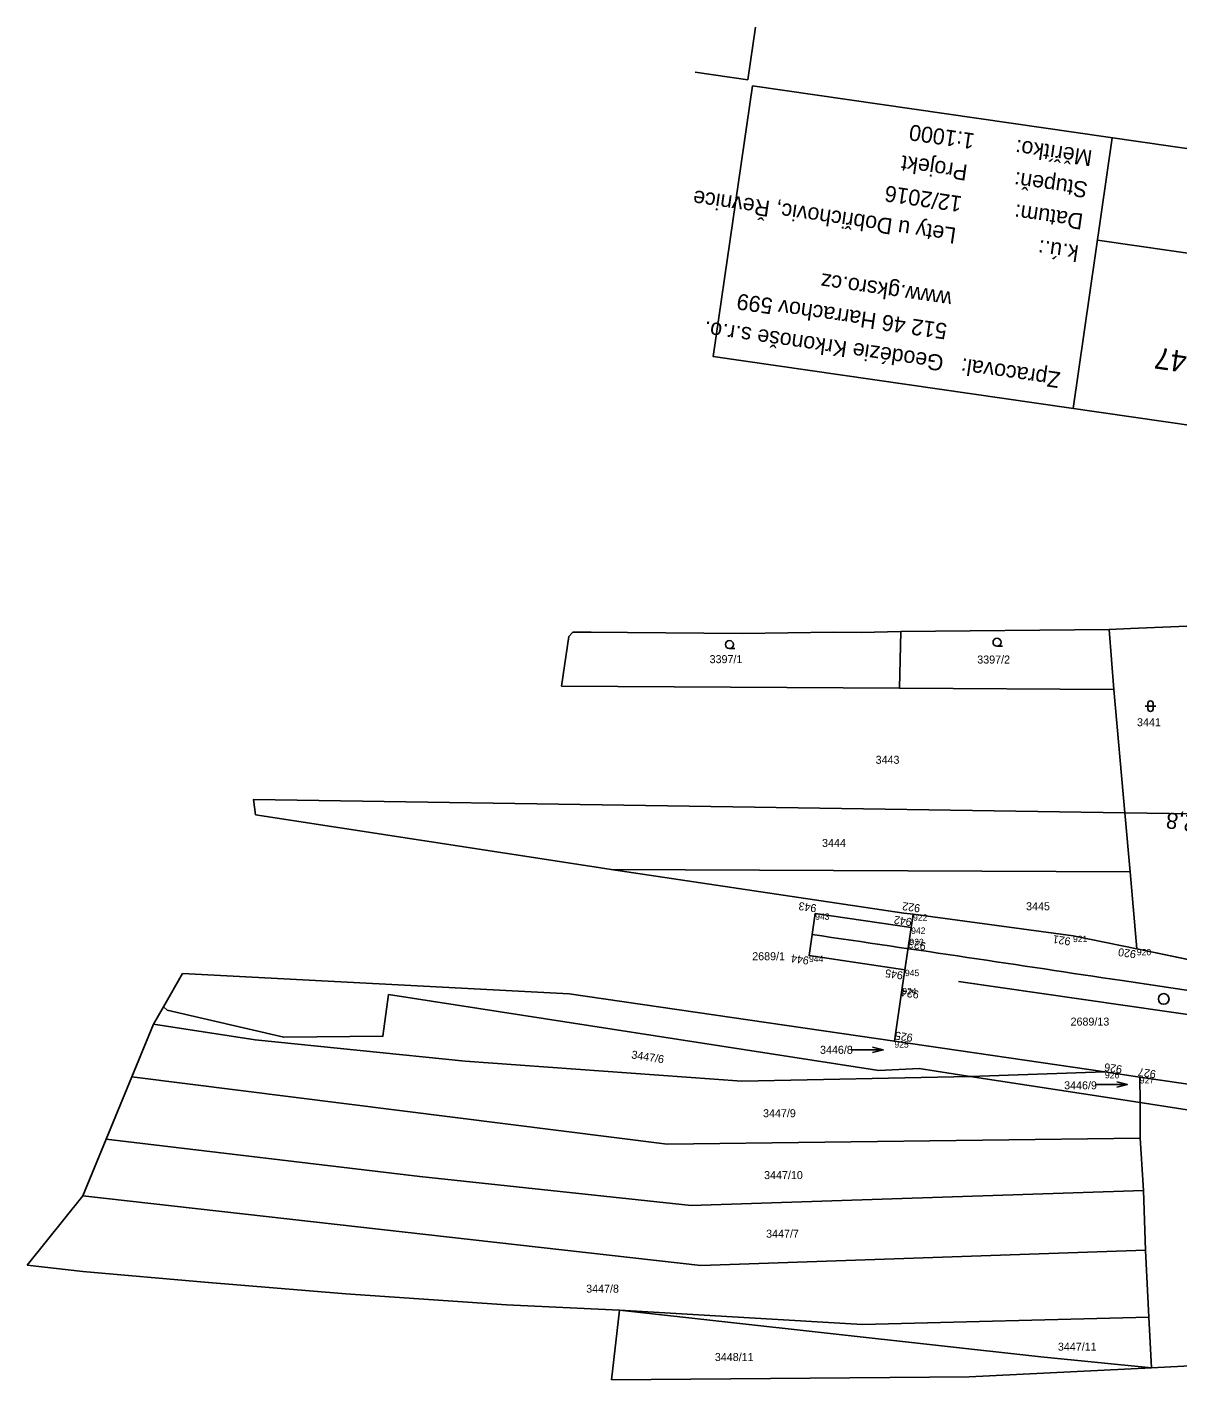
# Model space of a CAD drawing. Extents: x -757895 to -757311, y -1060303 to -1059942.
# Drawn here: x -757895.1 to -757679.5, y -1060195.2 to -1059941.6 of the extents above; entities that cross this region are included whole.
import ezdxf

# ---------------------------------------------------------------- set-up
doc = ezdxf.new("R2010")
doc.units = 0
for name, color, linetype in [('_hektaky', 7, 'Continuous'), ('_SO 102 hektometry', 7, 'Continuous'), ('Dočasné zábory', 7, 'Continuous'), ('Legenda 1', 7, 'Continuous'), ('Obvod stavby', 7, 'Continuous'), ('Vrstva 1', 7, 'Continuous'), ('Vrstva 53', 7, 'Continuous'), ('Vrstva 55', 7, 'Continuous'), ('Vrstva 57', 7, 'Continuous'), ('Vrstva 58', 7, 'Continuous'), ('Vrstva 60', 7, 'Continuous')]:
    doc.layers.add(name, color=color, linetype=linetype)

msp = doc.modelspace()

# ---------------------------------------------------------------- linework, layer by layer
at = {"layer": '_SO 102 hektometry'}
msp.add_circle((-757682.17, -1060123.76), 1, dxfattribs=at)
at = {"layer": 'Dočasné zábory'}
msp.add_lwpolyline([(-757730.65, -1060118.28), (-757729.8, -1060112.49), (-757729.49, -1060110.36), (-757747.46, -1060107.72), (-757748.62, -1060115.63), (-757730.65, -1060118.28)], dxfattribs=at)
at = {"layer": 'Legenda 1'}
for p, q in [((-757758.65, -1059941.6), (-757760.08, -1059951.5)), ((-757769.98, -1059950.07), (-757760.08, -1059951.5)), ((-757691.8, -1059962.36), (-757699.12, -1060013.09)), ((-757694.57, -1059981.56), (-757587.21, -1059997.05))]:
    msp.add_line(p, q, dxfattribs=at)
msp.add_lwpolyline([(-757759.23, -1059952.63), (-757584.43, -1059977.86), (-757591.76, -1060028.59), (-757766.56, -1060003.36)], close=True, dxfattribs=at)
at = {"layer": 'Obvod stavby'}
msp.add_lwpolyline([(-757639.93, -1060124.17), (-757687.19, -1060114.38), (-757699.16, -1060111.9), (-757729.12, -1060107.89), (-757729.8, -1060112.49), (-757731.15, -1060121.69), (-757732.62, -1060131.67), (-757693.18, -1060137.43), (-757686.64, -1060138.39), (-757635.44, -1060145.86)], dxfattribs=at)
at = {"layer": 'Vrstva 1'}
for p, q in [((-757429.32, -1060162.53), (-757720.62, -1060120.47)), ((-757665.26, -1060124.05), (-757689.98, -1060120.32))]:
    msp.add_line(p, q, dxfattribs=at)
msp.add_arc((-759559.14, -1072479.78), 12500, 81.400126, 81.669213, dxfattribs=at)
at = {"layer": 'Vrstva 53'}
for points in [[(-757852.31, -1060089.26), (-757789.66, -1060098.89), (-757785.7, -1060099.48), (-757730.83, -1060107.66), (-757729.12, -1060107.89), (-757699.16, -1060111.9), (-757687.19, -1060114.38), (-757639.93, -1060124.17)], [(-757328.56, -1060183.46), (-757338.29, -1060184.85), (-757361.91, -1060181.63), (-757443.58, -1060171.99), (-757470.38, -1060167.04), (-757513.1, -1060164.5), (-757526.21, -1060162.71), (-757533.6, -1060161.43), (-757535.01, -1060161.18), (-757542.9, -1060160.49), (-757543.88, -1060160.4), (-757632.1, -1060146.3), (-757634.26, -1060145.96), (-757635.44, -1060145.86), (-757686.64, -1060138.39), (-757693.18, -1060137.43), (-757732.62, -1060131.67), (-757793.56, -1060122.78), (-757866, -1060118.97)]]:
    msp.add_lwpolyline(points, dxfattribs=at)
at = {"layer": 'Vrstva 55'}
for p, q in [((-757688.39, -1060054.34), (-757677.84, -1060053.89)), ((-757794.99, -1060065.12), (-757793.62, -1060055.81)), ((-757761.16, -1060055.23), (-757782.62, -1060055.08)), ((-757731.45, -1060054.87), (-757738.86, -1060055.09)), ((-757731.69, -1060065.52), (-757731.45, -1060054.87)), ((-757692.38, -1060054.51), (-757731.45, -1060054.87)), ((-757692.38, -1060054.51), (-757688.39, -1060054.34)), ((-757691.5, -1060065.78), (-757692.38, -1060054.51)), ((-757794.99, -1060065.12), (-757731.69, -1060065.52)), ((-757731.69, -1060065.52), (-757691.5, -1060065.78)), ((-757691.5, -1060065.78), (-757689.45, -1060088.87)), ((-757689.45, -1060088.87), (-757688.47, -1060099.93)), ((-757689.45, -1060088.87), (-757676.88, -1060089.06)), ((-757785.7, -1060099.48), (-757688.47, -1060099.93)), ((-757688.47, -1060099.93), (-757687.19, -1060114.38)), ((-757687.19, -1060114.38), (-757639.93, -1060124.17)), ((-757869.56, -1060125.23), (-757866, -1060118.97)), ((-757866, -1060118.97), (-757793.56, -1060122.78)), ((-757793.56, -1060122.78), (-757732.62, -1060131.67)), ((-757871.42, -1060128.49), (-757869.56, -1060125.23)), ((-757875.47, -1060138.34), (-757871.42, -1060128.49)), ((-757693.18, -1060137.43), (-757732.62, -1060131.67)), ((-757718.41, -1060138.26), (-757693.18, -1060137.43)), ((-757686.64, -1060138.39), (-757693.18, -1060137.43)), ((-757880.28, -1060150.04), (-757875.47, -1060138.34)), ((-757718.41, -1060138.26), (-757686.61, -1060143.18)), ((-757686.61, -1060143.18), (-757686.64, -1060138.39)), ((-757686.57, -1060149.86), (-757686.61, -1060143.18)), ((-757884.65, -1060160.67), (-757880.28, -1060150.04)), ((-757685.97, -1060159.64), (-757686.57, -1060149.86)), ((-757685.61, -1060170.82), (-757685.97, -1060159.64)), ((-757895.12, -1060173.65), (-757884.65, -1060160.67)), ((-757684.97, -1060183.38), (-757685.61, -1060170.82)), ((-757884.69, -1060174.86), (-757895.12, -1060173.65)), ((-757861.86, -1060176.83), (-757884.69, -1060174.86)), ((-757835.37, -1060179.05), (-757861.86, -1060176.83)), ((-757805.28, -1060181.09), (-757835.37, -1060179.05)), ((-757784.15, -1060182.07), (-757805.28, -1060181.09)), ((-757785.65, -1060195.16), (-757784.15, -1060182.07)), ((-757684.44, -1060192.89), (-757684.97, -1060183.38))]:
    msp.add_line(p, q, dxfattribs=at)
for points in [[(-757782.62, -1060055.08), (-757789.45, -1060055.02), (-757792.84, -1060054.99), (-757793.62, -1060055.81)], [(-757738.86, -1060055.09), (-757744.02, -1060055.04), (-757761.16, -1060055.23)], [(-757852.31, -1060089.26), (-757852.72, -1060086.39), (-757689.45, -1060088.87)], [(-757785.7, -1060099.48), (-757789.66, -1060098.89), (-757852.31, -1060089.26)], [(-757729.12, -1060107.89), (-757730.83, -1060107.66), (-757785.7, -1060099.48)], [(-757732.62, -1060131.67), (-757731.15, -1060121.69), (-757729.8, -1060112.49), (-757729.12, -1060107.89)], [(-757729.12, -1060107.89), (-757699.16, -1060111.9), (-757687.19, -1060114.38)], [(-757869.56, -1060125.23), (-757868.9, -1060125.84), (-757847.02, -1060130.94), (-757828.46, -1060130.73), (-757827.38, -1060122.93), (-757735.56, -1060137.19), (-757727.96, -1060136.79), (-757718.41, -1060138.26)], [(-757871.42, -1060128.49), (-757852.4, -1060131.41), (-757813.07, -1060135.44), (-757761.18, -1060139.17), (-757718.41, -1060138.26)], [(-757875.47, -1060138.34), (-757775.17, -1060150.97), (-757686.57, -1060149.86)], [(-757634.26, -1060145.96), (-757635.44, -1060145.86), (-757686.64, -1060138.39)], [(-757686.61, -1060143.18), (-757664.14, -1060146.65), (-757658.56, -1060153.53), (-757630.94, -1060158.73)], [(-757685.97, -1060159.64), (-757770.72, -1060162.45), (-757821.53, -1060157.03), (-757880.28, -1060150.04)], [(-757884.65, -1060160.67), (-757768.87, -1060173.68), (-757685.61, -1060170.82)], [(-757784.15, -1060182.07), (-757738.63, -1060184.76), (-757684.97, -1060183.38)], [(-757784.15, -1060182.07), (-757705.21, -1060190.84), (-757684.44, -1060192.89)], [(-757785.65, -1060195.16), (-757718.62, -1060194.56), (-757684.44, -1060192.89)], [(-757684.44, -1060192.89), (-757656.46, -1060191.47), (-757636.9, -1060190.98)]]:
    msp.add_lwpolyline(points, dxfattribs=at)
at = {"layer": 'Vrstva 58'}
for p, q in [((-757763.52, -1060058.08), (-757762.52, -1060058.08)), ((-757713.4, -1060057.66), (-757712.4, -1060057.66)), ((-757685.65, -1060068.88), (-757683.65, -1060068.88)), ((-757685.15, -1060068.38), (-757685.15, -1060069.38)), ((-757684.15, -1060068.38), (-757684.15, -1060069.38)), ((-757740.7, -1060133.31), (-757734.7, -1060133.31)), ((-757694.98, -1060139.78), (-757688.98, -1060139.78))]:
    msp.add_line(p, q, dxfattribs=at)
for points in [[(-757736.7, -1060132.81), (-757734.7, -1060133.31), (-757736.7, -1060133.81)], [(-757690.98, -1060139.28), (-757688.98, -1060139.78), (-757690.98, -1060140.28)]]:
    msp.add_lwpolyline(points, dxfattribs=at)
for centre in [(-757713.4, -1060056.91), (-757763.52, -1060057.33)]:
    msp.add_circle(centre, 0.75, dxfattribs=at)
for centre, start, end in [((-757684.65, -1060068.38), 0, 180), ((-757684.65, -1060069.38), 180, 0)]:
    msp.add_arc(centre, 0.5, start, end, dxfattribs=at)
at = {"layer": 'Vrstva 60'}
for p, q in [((-757747.46, -1060107.72), (-757747.46, -1060107.72)), ((-757729.12, -1060107.89), (-757729.12, -1060107.89)), ((-757729.48, -1060110.36), (-757729.48, -1060110.36)), ((-757699.16, -1060111.9), (-757699.16, -1060111.9)), ((-757729.8, -1060112.49), (-757729.8, -1060112.49)), ((-757687.19, -1060114.38), (-757687.19, -1060114.38)), ((-757748.62, -1060115.63), (-757748.62, -1060115.63)), ((-757730.65, -1060118.28), (-757730.65, -1060118.28)), ((-757731.15, -1060121.69), (-757731.15, -1060121.69)), ((-757732.62, -1060131.67), (-757732.62, -1060131.67)), ((-757693.18, -1060137.43), (-757693.18, -1060137.43)), ((-757686.64, -1060138.39), (-757686.64, -1060138.39))]:
    msp.add_line(p, q, dxfattribs=at)

# ---------------------------------------------------------------- texts
at = {"layer": '_hektaky'}
msp.add_text('22,8', height=3, rotation=171.4001, dxfattribs=at).set_placement((-757673.76, -1060089.9))
at = {"layer": 'Dočasné zábory'}
for s, p in [('943', (-757747.13, -1060106.06)), ('942', (-757729.28, -1060108.64)), ('944', (-757748.55, -1060115.86)), ('945', (-757730.93, -1060118.64))]:
    msp.add_text(s, height=1.5, rotation=171.7882, dxfattribs=at).set_placement(p)
at = {"layer": 'Legenda 1'}
for s, p in [('Měřítko:       1:1000', (-757695.4, -1059964.75)), ('Stupeň:        Projekt', (-757696.26, -1059970.69)), ('k.ú.:              Lety u Dobřichovic, Řevnice', (-757697.97, -1059982.57)), ('Datum:         12/2016', (-757697.11, -1059976.63)), ('                    www.gksro.cz', (-757699.68, -1059994.45)), ('                    512 46 Harrachov 599', (-757700.54, -1060000.38)), ('Zpracoval:   Geodézie Krkonoše s.r.o.', (-757701.4, -1060006.32))]:
    msp.add_text(s, height=3, rotation=171.7882, dxfattribs=at).set_placement(p)
at = {"layer": 'Obvod stavby'}
for s, p in [('922', (-757727.7, -1060106.07)), ('921', (-757699.52, -1060112.27)), ('923', (-757726.63, -1060113.16)), ('920', (-757687.27, -1060114.68)), ('924', (-757727.94, -1060122.23)), ('925', (-757729.1, -1060130.33)), ('926', (-757689.88, -1060136.25)), ('927', (-757683.54, -1060137.16))]:
    msp.add_text(s, height=1.5, rotation=171.7882, dxfattribs=at).set_placement(p)
at = {"layer": 'Vrstva 55'}
msp.add_text('Rekonstrukce mostu v km 22,647', height=4, rotation=171.7882, dxfattribs=at).set_placement((-757604.96, -1060012.93))
at = {"layer": 'Vrstva 57'}
for s, p in [('3397/1', (-757767.24, -1060060.82)), ('3397/2', (-757717.1, -1060060.89)), ('3441', (-757687.17, -1060072.64)), ('3443', (-757736.14, -1060079.68)), ('3444', (-757746.18, -1060095.27)), ('3445', (-757707.95, -1060107.13)), ('2689/1', (-757759.26, -1060116.5)), ('2689/13', (-757699.62, -1060128.75)), ('3446/8', (-757746.56, -1060134.04)), ('3446/9', (-757700.82, -1060140.69)), ('3447/9', (-757757.23, -1060145.92)), ('3447/10', (-757757.04, -1060157.52)), ('3447/7', (-757756.66, -1060168.5)), ('3447/8', (-757790.37, -1060178.8)), ('3447/11', (-757701.99, -1060189.67)), ('3448/11', (-757766.26, -1060191.62))]:
    msp.add_text(s, height=1.5, dxfattribs=at).set_placement(p)
msp.add_text('3447/6', height=1.5, rotation=351, dxfattribs=at).set_placement((-757781.98, -1060134.88))
at = {"layer": 'Vrstva 60'}
for s, p in [('943', (-757747.46, -1060108.92)), ('922', (-757729.12, -1060109.09)), ('942', (-757729.48, -1060111.56)), ('921', (-757699.16, -1060113.1)), ('923', (-757729.8, -1060113.69)), ('920', (-757687.19, -1060115.58)), ('944', (-757748.62, -1060116.83)), ('945', (-757730.65, -1060119.48)), ('924', (-757731.15, -1060122.89)), ('925', (-757732.62, -1060132.87)), ('926', (-757693.18, -1060138.63)), ('927', (-757686.64, -1060139.59))]:
    msp.add_text(s, height=1.2, dxfattribs=at).set_placement(p)

doc.saveas('drawing.dxf')
